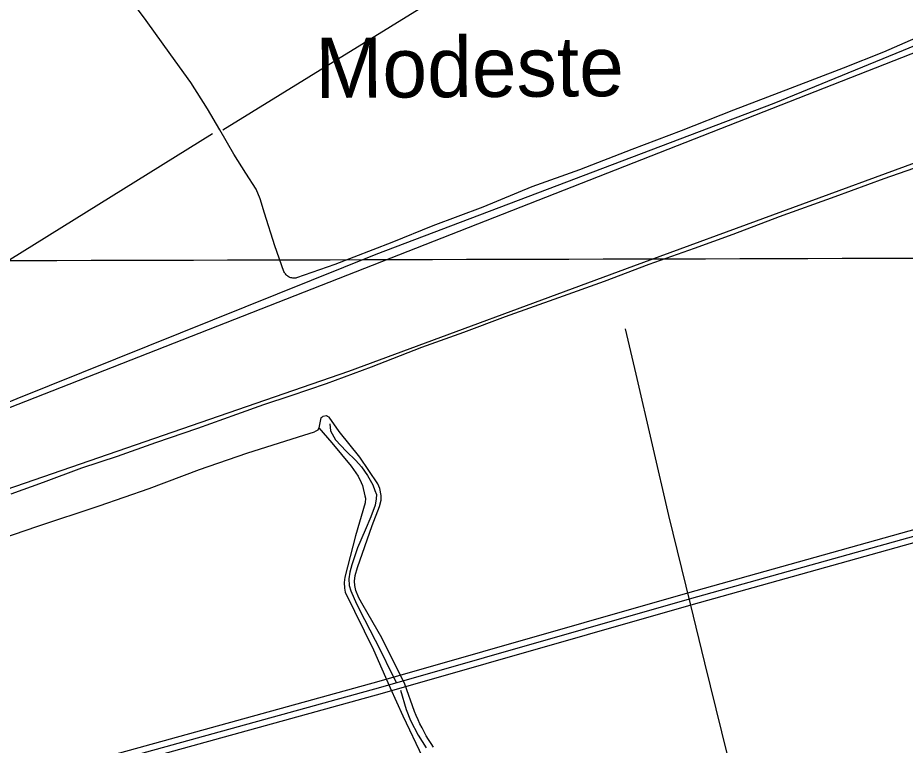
# Model space of a CAD drawing. Extents: x 3355724 to 3393621, y 594744 to 620174.
# Drawn here: x 3378091 to 3380230, y 605066 to 606819 of the extents above; entities that cross this region are included whole.
import ezdxf

# ---------------------------------------------------------------- set-up
doc = ezdxf.new("R2010")
doc.units = 0
for name, color, linetype in [('V-DTCH-CNTR', 7, 'Continuous'), ('V-GRID-MAJR', 7, 'Continuous'), ('V-ROAD-CNTR', 7, 'Continuous'), ('V-TOPO-GNAM-IDEN', 7, 'Continuous'), ('V-TOPO-SHOR', 7, 'Continuous'), ('V-UTIL-LINE', 7, 'Continuous')]:
    doc.layers.add(name, color=color, linetype=linetype)

msp = doc.modelspace()

# ---------------------------------------------------------------- linework, layer by layer
at = {"layer": 'V-DTCH-CNTR'}
for points in [[(3380268.1, 606775.1), (3380178.1, 606735.8), (3380080.2, 606697.7), (3379952.8, 606648.5), (3379816.5, 606596.6), (3379690.3, 606546.6), (3379571.1, 606501.8), (3379444.5, 606452.6), (3379329.9, 606411.6), (3379211.9, 606362.9), (3379091.5, 606317.3), (3378992.5, 606277.9), (3378855, 606224.8), (3378763, 606192.1), (3378760.7, 606191.7), (3378758.3, 606191.5), (3378756, 606191.4), (3378753.7, 606191.6), (3378751.4, 606192), (3378749.1, 606192.6), (3378746.9, 606193.3), (3378744.8, 606194.3), (3378742.7, 606195.5), (3378740.8, 606196.8), (3378739, 606198.3), (3378737.4, 606199.9), (3378735.9, 606201.7), (3378734.5, 606203.6), (3378733.3, 606205.6), (3378732.4, 606207.8), (3378710.5, 606269.3), (3378685.3, 606347.8), (3378675, 606382.7), (3378665.2, 606406), (3378640.1, 606444.8), (3378611.9, 606490.6), (3378577.4, 606548.8), (3378548.4, 606599.3), (3378508.1, 606662.9), (3378459.9, 606729.6), (3378400.4, 606812.2), (3378356.2, 606872.7)], [(3378074.5, 605671.7), (3378152.9, 605700), (3378245.4, 605734.2), (3378330.8, 605763), (3378423.7, 605795.7), (3378525, 605830), (3378618.6, 605864.2), (3378683.5, 605887.1), (3378749.9, 605909.1), (3378835, 605937.9), (3378943.7, 605978.1), (3379064.5, 606025.6), (3379166.3, 606061.5), (3379266.5, 606098.9), (3379395, 606144.6), (3379504.9, 606184.7), (3379612.5, 606225.6), (3379722.4, 606264.2), (3379815.6, 606297.7), (3379927.1, 606339.8), (3380061.5, 606388.6), (3380179.1, 606431.5), (3380287.5, 606469.3)], [(3379941.5, 603955.8), (3379935.5, 604166.2), (3379920.8, 604392.1), (3379880.2, 604684.5), (3379828.6, 604932.5), (3379746.8, 605265), (3379712.7, 605407.2), (3379660.4, 605620), (3379581.1, 605960.3), (3379555.8, 606069.7)], [(3379046.8, 605147.6), (3379023.5, 605213.2), (3378968.2, 605324.7), (3378923.5, 605402.9), (3378913, 605421.6), (3378906, 605438.9), (3378903.1, 605450.7), (3378902.4, 605461.1), (3378904.4, 605475), (3378909.9, 605494.4), (3378944.8, 605595.9), (3378962.7, 605641.1), (3378966.8, 605656.4), (3378966.7, 605667.5), (3378963.2, 605684.8), (3378959, 605695.9), (3378915, 605760.2), (3378865.4, 605821.8), (3378841.7, 605856.4), (3378837.5, 605858.4), (3378834.7, 605859.8), (3378826.4, 605858.4), (3378824.3, 605857), (3378821.6, 605854.9), (3378816.8, 605831.3), (3378814.1, 605825), (3378806.3, 605821.2)], [(3378816.8, 605831.3), (3378847.5, 605794.6), (3378894.3, 605738.6), (3378911, 605714.4), (3378918.7, 605699.2), (3378921.5, 605691.6), (3378927.2, 605667.3), (3378928.6, 605661.7), (3378927.9, 605650.6), (3378904.7, 605570.7), (3378879.5, 605471.4), (3378877.4, 605458.2), (3378878.2, 605444.3), (3378880.3, 605434.6), (3378948.2, 605296.1), (3378988.3, 605204.2), (3379019.1, 605137), (3379066, 605037.3)], [(3377997.6, 605545.4), (3378136.6, 605593.5), (3378286.6, 605643.2), (3378407.4, 605684.9), (3378528.5, 605730.2), (3378642.7, 605770), (3378767.4, 605809), (3378806.3, 605821.2)], [(3379092.8, 605061.5), (3379086.9, 605070.6), (3379081.1, 605079.8), (3379075.6, 605089.1), (3379070.3, 605098.6), (3379065.2, 605108.2), (3379060.2, 605117.9), (3379055.6, 605127.7), (3379051.1, 605137.6), (3379046.8, 605147.6)]]:
    msp.add_lwpolyline(points, dxfattribs=at)
at = {"layer": 'V-GRID-MAJR'}
msp.add_spline([(3359834, 606189.7), (3365100.7, 606201.5), (3370367.4, 606214.2), (3375634.1, 606227.6), (3380900.8, 606241.7), (3386167.5, 606256.7), (3391434.2, 606272.4)], degree=3, dxfattribs=at)
at = {"layer": 'V-ROAD-CNTR'}
for points in [[(3381854.6, 605977.8), (3381815.6, 606000.1), (3381743.3, 605986.2), (3380945.7, 605763.7), (3379709.2, 605418.2), (3378965, 605205.3), (3377553.8, 604815.8), (3376185.5, 604424.1), (3375177.3, 604130.8)], [(3380465.8, 605645.1), (3379705.1, 605432.6), (3378961, 605219.8), (3377549.8, 604830.2), (3376181.3, 604438.5), (3375173.2, 604145.2)], [(3380471.6, 605615.6), (3379713.3, 605403.7), (3378969.1, 605190.9), (3377557.9, 604801.3), (3377484.7, 604780.4)]]:
    msp.add_lwpolyline(points, dxfattribs=at)
at = {"layer": 'V-TOPO-SHOR'}
msp.add_line((3378560, 606539.5), (3377767.2, 606046.8), dxfattribs=at)
for points in [[(3379913.2, 607366.2), (3379058.1, 606840.1), (3378584.9, 606547.8)], [(3380256.2, 606752.8), (3379913.6, 606612.6), (3378954.2, 606248.4), (3378088.3, 605901.1), (3377843.2, 605798.6)], [(3377802.2, 605588.6), (3377906, 605628.3), (3378888.4, 605967.6), (3379575.8, 606221), (3380294.3, 606484.8)], [(3378843.2, 605840.7), (3378844.4, 605824), (3378856.6, 605802.3), (3378882, 605775.1), (3378905.4, 605752.3), (3378919.5, 605737.2), (3378934, 605715.9), (3378946.5, 605693.3), (3378951.6, 605680.1), (3378955.2, 605670), (3378954.8, 605659.5), (3378952.5, 605644.4), (3378941.8, 605616.7), (3378928.3, 605584.7), (3378909.8, 605541.9), (3378895.6, 605500.6), (3378891, 605483.4), (3378888.4, 605466.7), (3378889.6, 605450.8), (3378893.9, 605437.9), (3378906.9, 605406.9), (3378926.5, 605368.8), (3378965, 605294.3), (3378991.6, 605239.6), (3379003, 605217.7)], [(3379013, 605198.6), (3379026.6, 605152.6), (3379037.3, 605125.4), (3379056.1, 605090.5), (3379074.9, 605059.9)]]:
    msp.add_lwpolyline(points, dxfattribs=at)
at = {"layer": 'V-UTIL-LINE'}
msp.add_lwpolyline([(3390588.5, 612579.5), (3390451.6, 612673.7), (3390299.5, 612751.6), (3389959.8, 612680.5), (3389847, 612538), (3385533.4, 609593.1), (3385499.6, 609602.1), (3383567, 608497.8), (3381617.2, 607432.4), (3381405.4, 607326.4), (3381328.6, 607207.6), (3381237.1, 607156), (3381225.1, 607117.1), (3377817.4, 605780.1), (3376938.3, 605435.9), (3376895.1, 605351.8), (3376042.4, 605046.4), (3373869.8, 603434.1), (3369595.2, 603170.4)], dxfattribs=at)

# ---------------------------------------------------------------- texts
at = {"layer": 'V-TOPO-GNAM-IDEN'}
msp.add_text('Modeste', height=145, rotation=0.3574, dxfattribs=at).set_placement((3378808.5, 606625.6))

doc.saveas('drawing.dxf')
